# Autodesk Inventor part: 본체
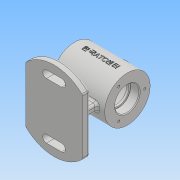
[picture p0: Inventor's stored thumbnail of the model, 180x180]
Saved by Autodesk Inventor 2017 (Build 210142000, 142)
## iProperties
Part Number: 본체
Material: 일반
Document SubType Name: Modeling
Designer: user
Density: 1 g/cm^3
Appearance: 기본값
Mass: 173.421 g
Surface Area: 486.995 cm^2
Volume: 173.421 cm^3
Author: user
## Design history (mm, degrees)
sketch "스케치1"
  geometry: C1 r 30 at (0, 0); 1 further point
  constraints: 1 centre point, 1 coincident
  dimensions: "d0" = 60 diameter of C1
extrude "돌출1" new body sketch "스케치1" stored distance "d1" = 70; taper "d2" = 0 deg
sketch "스케치2"
  geometry: C1 r 30 at (0, 0) reference; C2 r 16 at (0, 0)
  constraints: 1 centre point, 1 coincident
  dimensions: "d3" = 32 diameter of C2
extrude "돌출2" cut sketch "스케치2" distance "d4" = 12; taper "d5" = 0 deg
sketch "스케치3"
  geometry: C1 r 16 at (0, 0) reference; C2 r 14 at (0, 0)
  constraints: 1 centre point, 1 coincident
  dimensions: "d6" = 28 diameter of C2
extrude "돌출3" cut sketch "스케치3" stored distance "d7" = 0; taper "d8" = 0 deg
sketch "스케치4"
  geometry: C1 r 25 at (0, 0); 1 further point
  constraints: 1 centre point, 1 coincident
  dimensions: "d9" = 50 diameter of C1
extrude "돌출4" cut sketch "스케치4" stored distance "d10" = 40; taper "d11" = 0 deg
fillet "모깎기1" dims "d12" = 3
chamfer "모따기1" distance "d13" = 1; stored, may be unused: second distance "d14" = 2, angle "d15" = 45 deg
node "작업 평면1"
sketch "스케치5"
  geometry: C1 r 10 at (0, 0); 1 further point
  constraints: 1 centre point, 1 coincident
  dimensions: "d17" = 20 diameter of C1
extrude "돌출5" join sketch "스케치5" stored distance "d18" = 40; taper "d19" = 0 deg
sketch "스케치6"
  geometry: C1 r 10 at (0, 0) reference; 1 further point
  constraints: 1 coincident
hole "구멍1" sketch "스케치6" at (0, 0) diameter "d20" = 10.106; stored, may be unused: countersink angle "d24" = 90 deg, drill point angle "d26" = 118 deg; dims "d21" = 24, "d22" = 4, "d23" = 2, "d25" = 32.3
node "작업 평면2"
sketch "스케치7"
  geometry: C1 r 52.5 at (0, 0); 1 further point
  constraints: 1 centre point, 1 coincident
  dimensions: "d28" = 105 diameter of C1
extrude "돌출6" join sketch "스케치7" distance "d29" = 10; taper "d30" = 0 deg
sketch "스케치8"
  geometry: L1 (37.5, -50)-(67.5, -50); L2 (67.5, -50)-(67.5, 50); L3 (67.5, 50)-(37.5, 50); L4 (37.5, 50)-(37.5, -50); L5 (37.5, -50)-(67.5, 50); L6 (67.5, -50)-(37.5, 50); L7 (-67.5, 50)-(-37.5, 50); L8 (-37.5, 50)-(-37.5, -50); L9 (-37.5, -50)-(-67.5, -50); L10 (-67.5, -50)-(-67.5, 50); L11 (-67.5, 50)-(-37.5, -50); L12 (-37.5, 50)-(-67.5, -50); C1 r 52.5 at (0, 0) reference; 4 further points
  constraints: 24 end point, 6 midpoint, 4 parallel, 2 horizontal, 2 horizontal alignment, 2 perpendicular
  dimensions: "d31" = 30 distance of L3.end L2.end; "d32" = 100 distance of L2.end L1.end; "d33" = 30 distance of L7.start L7.end; "d34" = 100 distance of L7.end L8.end; "d36" = 37.5 distance from line of C1.centre L4; "d37" = 37.5 distance from line of C1.centre L8
extrude "돌출7" cut sketch "스케치8" stored distance "d38" = 10; taper "d39" = 0 deg
sketch "스케치9"
  geometry: L1 (-25, -5)-(25, -5); L2 (25, -5)-(25, 5); L3 (25, 5)-(-25, 5); L4 (-25, 5)-(-25, -5); L5 (-25, -5)-(25, 5); L6 (25, -5)-(-25, 5); A1 r 52.5 centre (0, 0) between (37.5, 36.742) and (-37.5, 36.742) reference
  constraints: 12 end point, 2 midpoint, 2 parallel, 1 horizontal, 1 perpendicular
  dimensions: "d40" = 50 distance of L2.end L3.end; "d41" = 10 distance of L1.end L2.end
extrude "돌출8" join sketch "스케치9" stored distance "d42" = 10; taper "d43" = 0 deg
sketch "스케치10"
  geometry: L1 (-10, 37)-(10, 37); L2 (-10, 32)-(10, 32); L3 (10, 42)-(-10, 42); A1 r 52.5 centre (0, 0) between (-37.5, -36.742) and (37.5, -36.742) reference; A2 r 5 centre (-10, 37) between (-10, 42) and (-10, 32); A3 r 5 centre (10, 37) between (10, 32) and (10, 42); 1 further point
  constraints: 8 end point, 4 point on circle, 4 tangent, 2 centre point, 1 horizontal, 1 midpoint, 1 parallel, 1 vertical alignment
  dimensions: "d44" = 20 distance of L1.start L1.end; "d45" = 10 diameter of A3; "d46" = 37 distance of A1.centre point (0, 37)
extrude "돌출9" cut sketch "스케치10" stored distance "d47" = 10; taper "d48" = 0 deg
sketch "스케치11"
  geometry: C1 r 30 at (0, 0) reference; 1 further point
  constraints: 1 vertical alignment
  dimensions: "d49" = 23 distance of C1.centre point (0, 23)
hole "구멍2" sketch "스케치11" at (0, 23) diameter "d50" = 3.242; stored, may be unused: countersink angle "d54" = 90 deg, drill point angle "d56" = 118 deg; dims "d51" = 8, "d52" = 4, "d53" = 2, "d55" = 10
node "작업 평면3"
sketch "스케치12"
  geometry: L1 (-35, 30)-(-35, -30) reference; L2 (-35, 30)-(35, 30) reference; 2 further points
  constraints: 1 other
  dimensions: "d60" = 35 distance from line of L1 point (0, 0); "d61" = 30 distance from line of L2 point (0, 0)
feature "엠보싱1" sketch "스케치12" dims "d9" = 50, "d62" = 0.5, "d63" = 0
fillet "모깎기2" dims "d64" = 3
fillet "모깎기3" dims "d65" = 3
fillet "모깎기4" dims "d66" = 3
fillet "모깎기5" dims "d67" = 3
fillet "모깎기6" dims "d68" = 3
fillet "모깎기7" dims "d69" = 3
fillet "모깎기8" dims "d70" = 0.3
node "솔리드1"
mirror "미러1"
mirror "미러2"
pattern_circular "원형 패턴1" dims angle "d58" = 360 deg
mirror "미러3"
other parameters: "d16" = 33, "d27" = -62
